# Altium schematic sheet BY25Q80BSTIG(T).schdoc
size 127 x 101 mm
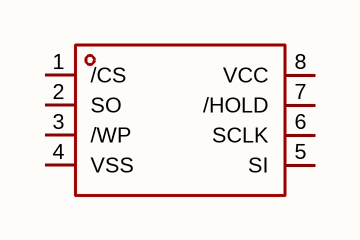
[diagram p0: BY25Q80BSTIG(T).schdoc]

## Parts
U?  by25q80bstig(t)  [SOP-8_L5.0-W4.0-P1.27-LS6.0-BL]  (value not drawn)

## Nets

Not connected (* = marked no-connect by the designer): U? 1(/CS) 2(SO) 3(/WP) 4(VSS) 5(SI) 6(SCLK) 7(/HOLD) 8(VCC)

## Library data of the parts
U? = by25q80bstig(t): 接口类型:SPI;存储容量:8Mbit;时钟频率(fc):108MHz;; Manufacturer: BOYAMICRO(博雅); AddInBom: yes; ModelId: a3315c1c78f949e6bb82c6eaca1c53c7; ModelName: SOP-8_L5.0-W4.0-H1.8-LS6.2-P1.27; ModelTransform: 244.094,196.85,0,90,0,0,0,0,0; Interface: SPI; Memory Size: 8Mbit; Clock Frequency: 108MHz; Voltage - Supply: 2.7V~3.6V; Standby Supply Current: 5uA; Program / Erase Cycles: 100000次; Page Programming Time (Tpp): 600us; Data Retention - TDR (Year): 20年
